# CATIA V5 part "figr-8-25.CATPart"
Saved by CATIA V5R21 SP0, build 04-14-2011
Part number: Part1
Bounding box of the stored display mesh (mm): x -50 to 50, y -62.5 to 62.5, z 0 to 10
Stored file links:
  D:\CATIA V5R21 E-RESOURCES\CATIA-V5R21\catia-v5r21-prt\c08-catia-v5r20-prt\c08-catia-v5r21-figr-8-25.CATPart
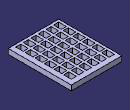
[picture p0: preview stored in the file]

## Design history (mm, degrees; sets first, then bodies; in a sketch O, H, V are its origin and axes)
Body1 (main body)
  Sketch1 on xy-plane, origin (0, 0, 0), H (1, 0, 0), V (0, 1, 0)
    line L1 (-50, 62.5) -> (50, 62.5)
    line L2 (50, 62.5) -> (50, -62.5)
    line L3 (50, -62.5) -> (-50, -62.5)
    line L4 (-50, -62.5) -> (-50, 62.5)
    axis line L5 (50, -62.5) -> (-50, 62.5)
    length L3 = 100
    length L2 = 125
    horizontal: L1 H, L3 H
    vertical: L2 V, L4 V
    midpoint: O L5
  Pad1: profile Sketch1, direction (0, 0, 1), length 10
  Sketch2 on face of Pad1, origin (0, 0, 10), H (1, 0, 0), V (0, 1, 0)
    line L1 (40, -57.5) -> (30, -57.5)
    line L2 (30, -57.5) -> (30, -42.5)
    line L3 (30, -42.5) -> (40, -42.5)
    line L4 (40, -42.5) -> (40, -57.5)
    reference projected line E1 (-50, -62.5) -> (50, -62.5) from edge [face of Pad1 | face of Pad1]
    reference projected line E2 (50, -62.5) -> (50, 62.5) from edge [face of Pad1 | face of Pad1]
    length L1 = 10
    length L4 = 15
    distance L1 E1 = 5
    distance L4 E2 = 10
    horizontal: L1 H, L3 H
    vertical: L2 V, L4 V
  Pocket1: profile Sketch2, direction (0, 0, -1), through (limit type 3)
  RectPattern1: of Pocket1, direction 1 instances 6, spacing 19, along edge [face of Pad1 | face of Pad1], direction 2 instances 6, spacing 15, along edge [face of Pad1 | face of Pad1] reversed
